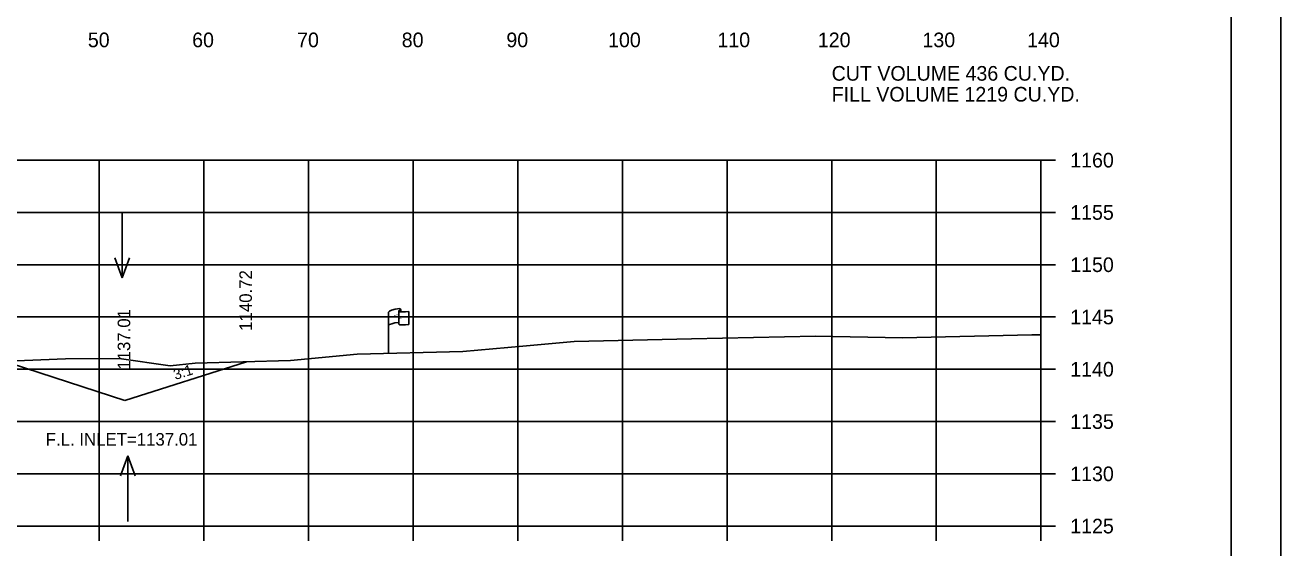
# Model space of a CAD drawing. Extents: x 1368971 to 1374497, y 378717 to 381839.
# Drawn here: x 1369685.8 to 1369805.9, y 379167.1 to 379217.1 of the extents above; entities that cross this region are included whole.
import ezdxf

# ---------------------------------------------------------------- set-up
doc = ezdxf.new("R2010")
doc.units = 0
for name, color, linetype in [('E_Existing ROW', 7, 'Continuous'), ('R_Axis', 7, 'Continuous'), ('R_Axis Annot', 7, 'Continuous'), ('R_Border', 7, 'Continuous'), ('R_Exist Surface', 7, 'Continuous'), ('R_Fin Surface', 7, 'Continuous'), ('R_Grid', 7, 'Continuous'), ('R_No Plot', 7, 'Continuous'), ('R_Water Annot', 7, 'Continuous'), ('R_Xsect Elev', 7, 'Continuous'), ('R_Xsect Slope', 7, 'Continuous')]:
    doc.layers.add(name, color=color, linetype=linetype)

msp = doc.modelspace()

# ---------------------------------------------------------------- linework, layer by layer
at = {"layer": 'E_Existing ROW'}
for p, q in [((1369720.58, 379185.66), (1369720.58, 379189.61)), ((1369721.57, 379189.71), (1369721.57, 379189.69)), ((1369721.57, 379189.69), (1369721.57, 379188.47)), ((1369721.74, 379189.86), (1369721.74, 379189.62)), ((1369722.51, 379189.67), (1369722.51, 379188.43))]:
    msp.add_line(p, q, dxfattribs=at)
for centre, radius, start, end in [((1369721.65, 379189.71), 0.078, 88.6458, 274.2828), ((1369721.66, 379189.86), 0.0783, 263.0712, 93.9564), ((1369721.65, 379188.47), 0.0783, 180, 273.9564)]:
    msp.add_arc(centre, radius, start, end, dxfattribs=at)
for centre, major_axis, ratio, start_param, end_param in [((1369722.16, 379189.65), (-1.58, -0.04), 0.19887, 5.030368, 6.283185), ((1369722.87, 379189.77), (-1.23, -0.13), 0.052933, 0.159456, 1.268315), ((1369722.15, 379188.34), (-1.58, -0.04), 0.19887, 5.083035, 6.194897), ((1369722.87, 379188.53), (-1.23, -0.13), 0.052933, 0.159456, 1.268315)]:
    msp.add_ellipse(centre, major_axis=major_axis, ratio=ratio, start_param=start_param, end_param=end_param, dxfattribs=at)
at = {"layer": 'R_Axis'}
for p, q in [((1369782.93, 379169.14), (1369782.93, 379204.14)), ((1369784.33, 379204.14), (1369782.93, 379204.14)), ((1369784.33, 379199.14), (1369782.93, 379199.14)), ((1369784.33, 379194.14), (1369782.93, 379194.14)), ((1369784.33, 379189.14), (1369782.93, 379189.14)), ((1369784.33, 379184.14), (1369782.93, 379184.14)), ((1369784.33, 379179.14), (1369782.93, 379179.14)), ((1369784.33, 379174.14), (1369782.93, 379174.14)), ((1369502.93, 379169.14), (1369782.93, 379169.14)), ((1369692.93, 379167.74), (1369692.93, 379169.14)), ((1369702.93, 379167.74), (1369702.93, 379169.14)), ((1369712.93, 379167.74), (1369712.93, 379169.14)), ((1369722.93, 379167.74), (1369722.93, 379169.14)), ((1369732.93, 379167.74), (1369732.93, 379169.14)), ((1369742.93, 379167.74), (1369742.93, 379169.14)), ((1369752.93, 379167.74), (1369752.93, 379169.14)), ((1369762.93, 379167.74), (1369762.93, 379169.14)), ((1369772.93, 379167.74), (1369772.93, 379169.14)), ((1369782.93, 379167.74), (1369782.93, 379169.14)), ((1369784.33, 379169.14), (1369782.93, 379169.14))]:
    msp.add_line(p, q, dxfattribs=at)
at = {"layer": 'R_Border'}
msp.add_line((1369801.11, 379079.14), (1369801.11, 379284.6), dxfattribs=at)
at = {"layer": 'R_Exist Surface'}
msp.add_lwpolyline([(1369668.59, 379184.29), (1369689.7, 379185.13), (1369694.83, 379185.18), (1369699.7, 379184.48), (1369702.1, 379184.73), (1369711.21, 379184.98), (1369717.59, 379185.58), (1369727.69, 379185.84), (1369733.41, 379186.35), (1369738.32, 379186.78), (1369749.53, 379187.04), (1369761.37, 379187.31), (1369769.7, 379187.13), (1369782.07, 379187.44), (1369782.93, 379187.43)], dxfattribs=at)
at = {"layer": 'R_Fin Surface'}
for p, q in [((1369670.88, 379189.09), (1369695.39, 379181.15)), ((1369695.39, 379181.15), (1369706.99, 379184.86))]:
    msp.add_line(p, q, dxfattribs=at)
at = {"layer": 'R_Grid'}
for p, q in [((1369502.93, 379204.14), (1369782.93, 379204.14)), ((1369692.93, 379169.14), (1369692.93, 379204.14)), ((1369702.93, 379169.14), (1369702.93, 379204.14)), ((1369712.93, 379169.14), (1369712.93, 379204.14)), ((1369722.93, 379169.14), (1369722.93, 379204.14)), ((1369732.93, 379169.14), (1369732.93, 379204.14)), ((1369742.93, 379169.14), (1369742.93, 379204.14)), ((1369752.93, 379169.14), (1369752.93, 379204.14)), ((1369762.93, 379169.14), (1369762.93, 379204.14)), ((1369772.93, 379169.14), (1369772.93, 379204.14)), ((1369782.93, 379169.14), (1369782.93, 379204.14)), ((1369502.93, 379199.14), (1369782.93, 379199.14)), ((1369502.93, 379194.14), (1369782.93, 379194.14)), ((1369502.93, 379189.14), (1369782.93, 379189.14)), ((1369502.93, 379184.14), (1369782.93, 379184.14)), ((1369502.93, 379179.14), (1369782.93, 379179.14)), ((1369502.93, 379174.14), (1369782.93, 379174.14)), ((1369502.93, 379169.14), (1369782.93, 379169.14))]:
    msp.add_line(p, q, dxfattribs=at)
at = {"layer": 'R_No Plot'}
for points in [[(1369472.52, 379288.5), (1369805.86, 379288.5), (1369805.86, 379075.16), (1369472.52, 379075.16)], [(1369718.85, 379284.6), (1369718.85, 379274.72), (1369754.58, 379274.72), (1369754.58, 379271.8), (1369777.78, 379271.8), (1369777.78, 379248.59), (1369801.11, 379248.59), (1369801.11, 379079.14), (1369484.93, 379079.14), (1369484.93, 379284.6)]]:
    msp.add_lwpolyline(points, close=True, dxfattribs=at)
at = {"layer": 'R_Water Annot'}
for p, q in [((1369695.13, 379199.17), (1369695.12, 379192.88)), ((1369695.12, 379192.88), (1369694.42, 379194.81)), ((1369695.12, 379192.88), (1369695.82, 379194.8)), ((1369695.67, 379175.87), (1369694.97, 379173.94)), ((1369695.67, 379169.58), (1369695.67, 379175.87)), ((1369695.67, 379175.87), (1369696.37, 379173.94))]:
    msp.add_line(p, q, dxfattribs=at)

# ---------------------------------------------------------------- texts
at = {"layer": 'E_Existing ROW'}
for s, height, rotation, p in [('DWB 11-9-07', 0.001, 90, (1369721.74, 379189.62)), ('R ', 0.2, 9.9884, (1369721.1, 379189.11)), (' O', 0.2, 9.9884, (1369721.24, 379189.16)), ('W', 0.2, 351.1788, (1369721.57, 379188.99)), ('DWB 11-9-07', 0.001, 5.0717, (1369722.5, 379188.43)), ('DWB 11-9-07', 0.001, 90, (1369720.58, 379185.66))]:
    msp.add_text(s, height=height, rotation=rotation, dxfattribs=at).set_placement(p)
at = {"layer": 'R_Axis Annot'}
for s, p in [('50', (1369691.84, 379214.94)), ('60', (1369701.81, 379214.94)), ('70', (1369711.84, 379214.94)), ('80', (1369721.84, 379214.94)), ('90', (1369731.84, 379214.94)), ('100', (1369741.56, 379214.94)), ('110', (1369752.01, 379214.94)), ('120', (1369761.61, 379214.94)), ('130', (1369771.61, 379214.94)), ('140', (1369781.61, 379214.94)), ('CUT VOLUME 436 CU.YD.', (1369762.93, 379211.74)), ('FILL VOLUME 1219 CU.YD.', (1369762.93, 379209.74)), ('1160', (1369785.73, 379203.44)), ('1155', (1369785.73, 379198.44)), ('1150', (1369785.73, 379193.44)), ('1145', (1369785.73, 379188.44)), ('1140', (1369785.73, 379183.44)), ('1135', (1369785.73, 379178.44)), ('1130', (1369785.73, 379173.44)), ('1125', (1369785.73, 379168.44))]:
    msp.add_text(s, height=1.4, dxfattribs=at).set_placement(p)
at = {"layer": 'R_Water Annot'}
msp.add_text('F.L. INLET=1137.01', height=1.2, dxfattribs=at).set_placement((1369687.82, 379176.84))
at = {"layer": 'R_Xsect Elev'}
for s, p in [('1140.72', (1369707.52, 379187.82)), ('1137.01', (1369695.89, 379184.1))]:
    msp.add_text(s, height=1.2, rotation=90, dxfattribs=at).set_placement(p)
at = {"layer": 'R_Xsect Slope'}
msp.add_text('3:1', height=1, rotation=17.7481, dxfattribs=at).set_placement((1369700.2, 379183.11))

doc.saveas('drawing.dxf')
